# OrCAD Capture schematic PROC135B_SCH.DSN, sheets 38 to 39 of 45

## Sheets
38 38. CSI INTERFACE: size C; title: SOC CSI INTERFACE,  BIDIRECTIONAL PASSIVE SWITCH AND CAMERA CONNECTOR
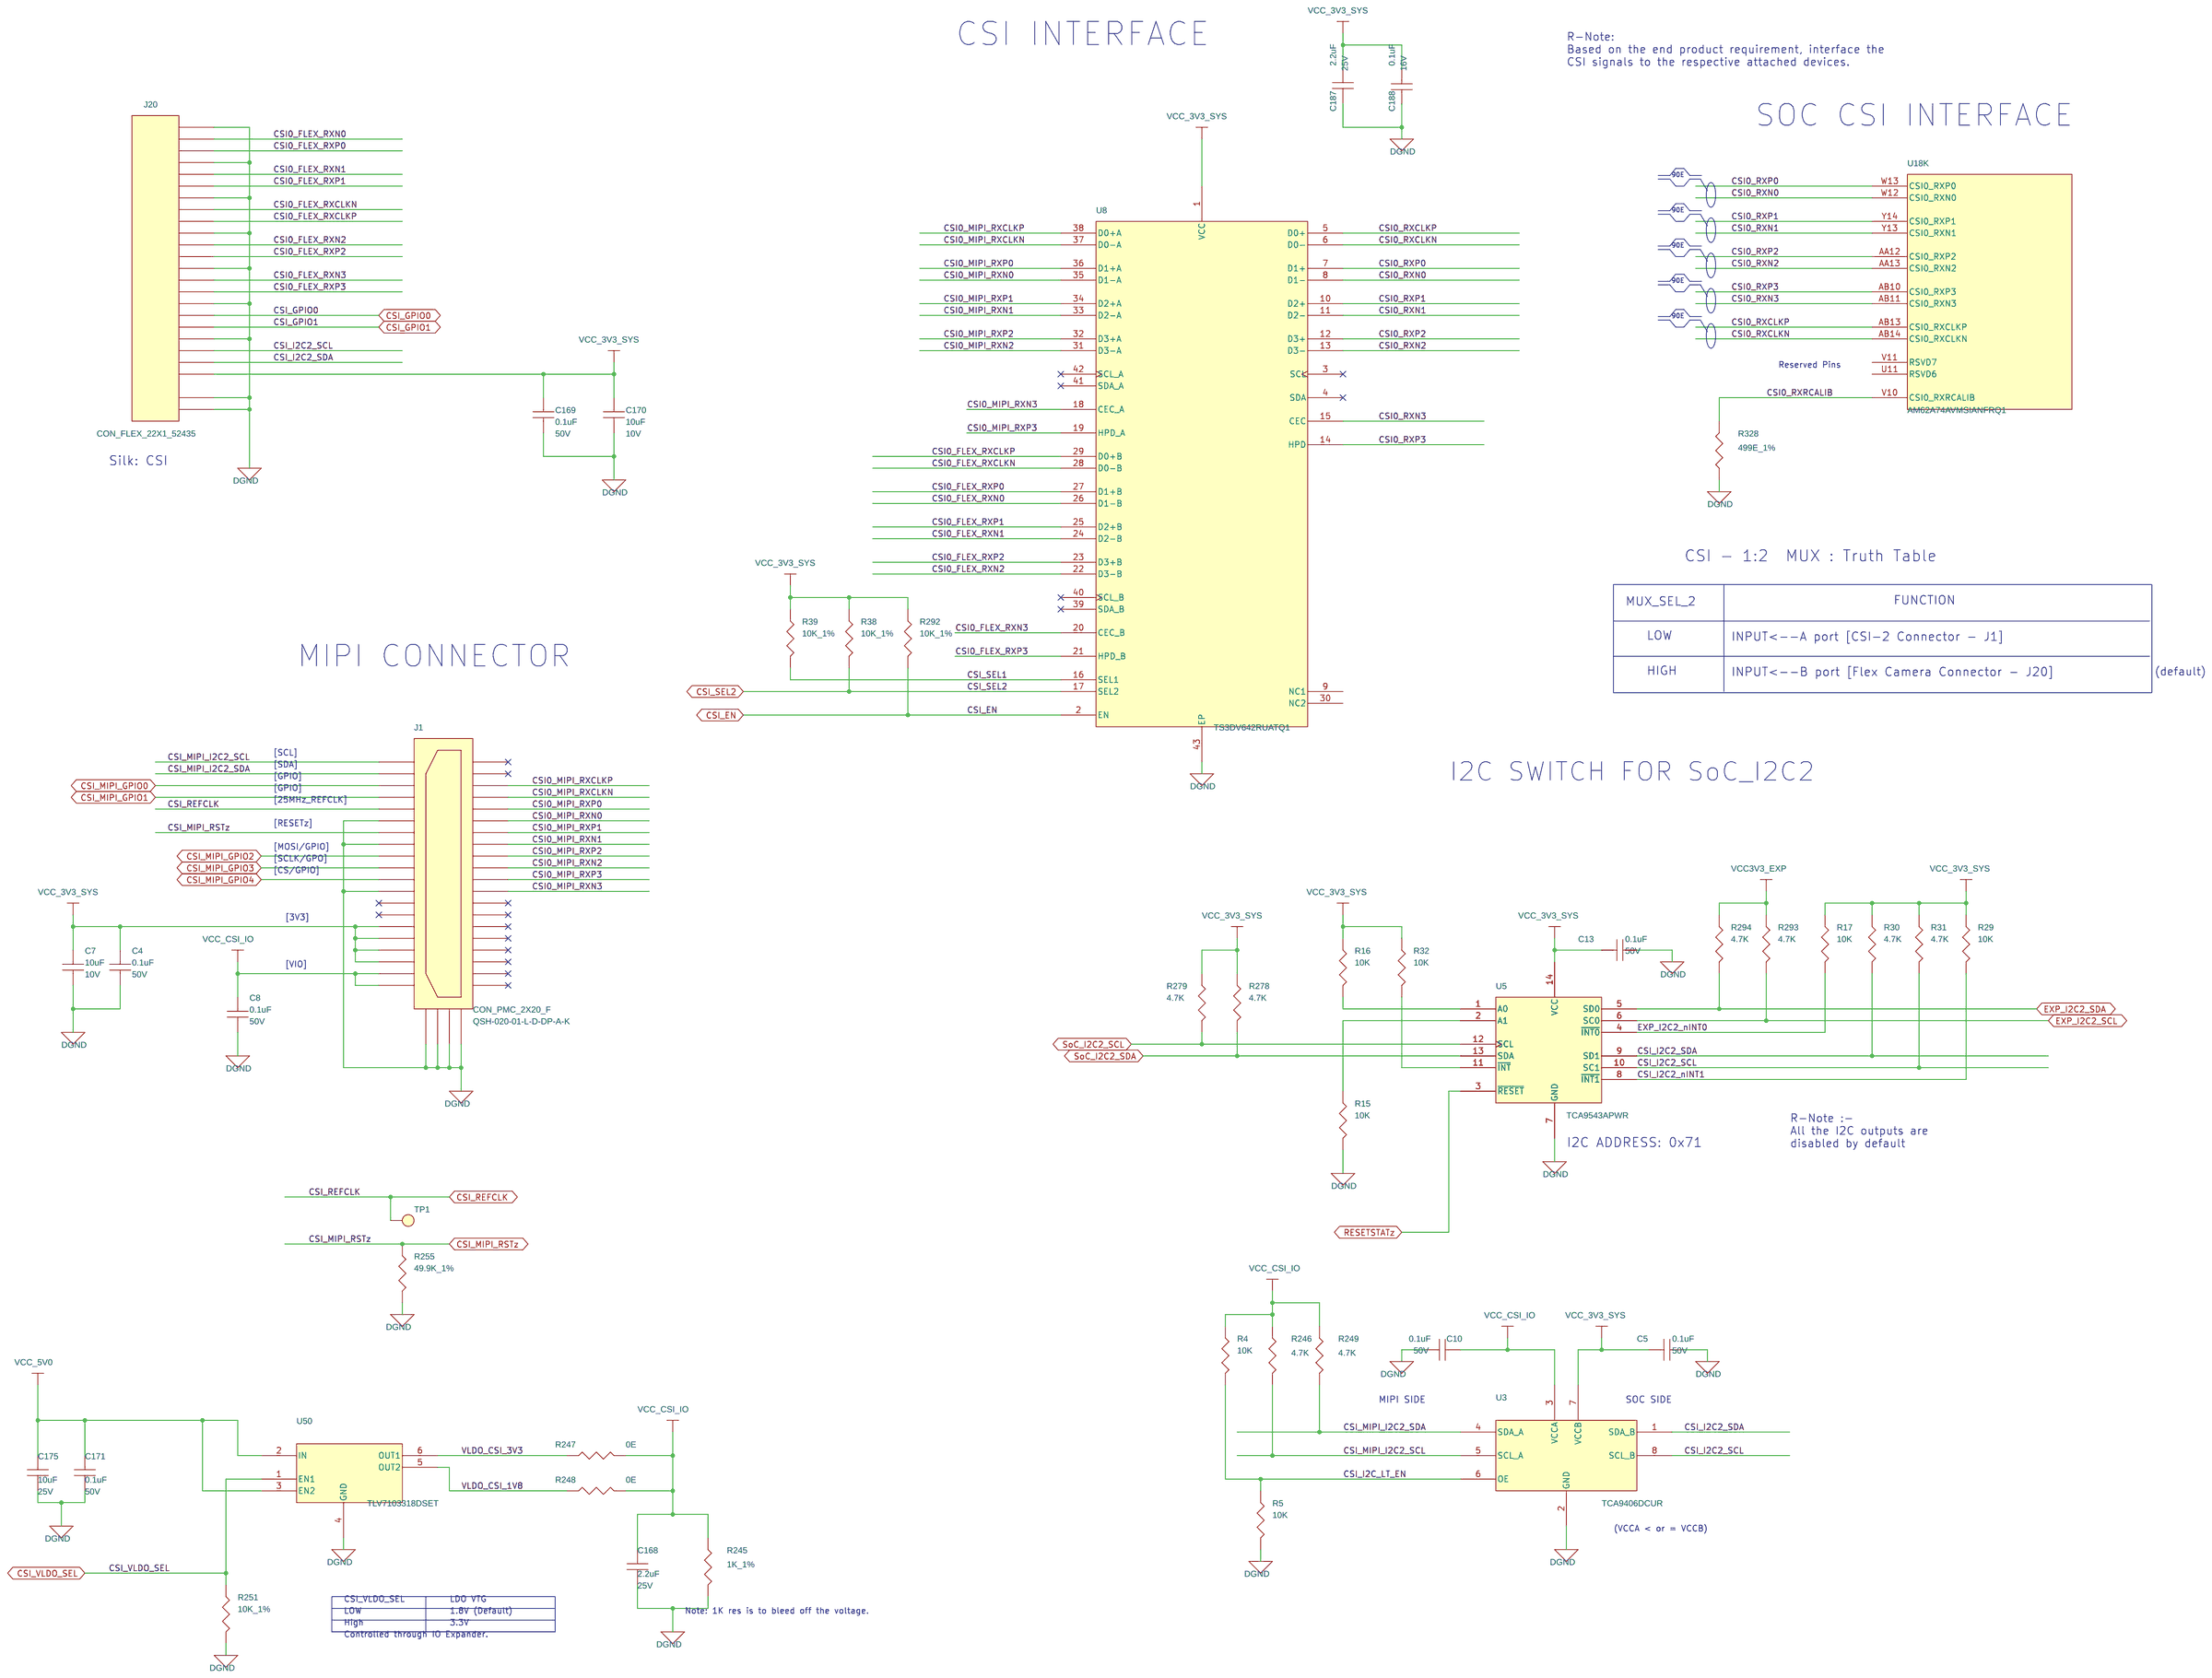
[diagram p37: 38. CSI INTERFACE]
39 39. AUDIO CODEC: size C; title: AUDIO CODEC
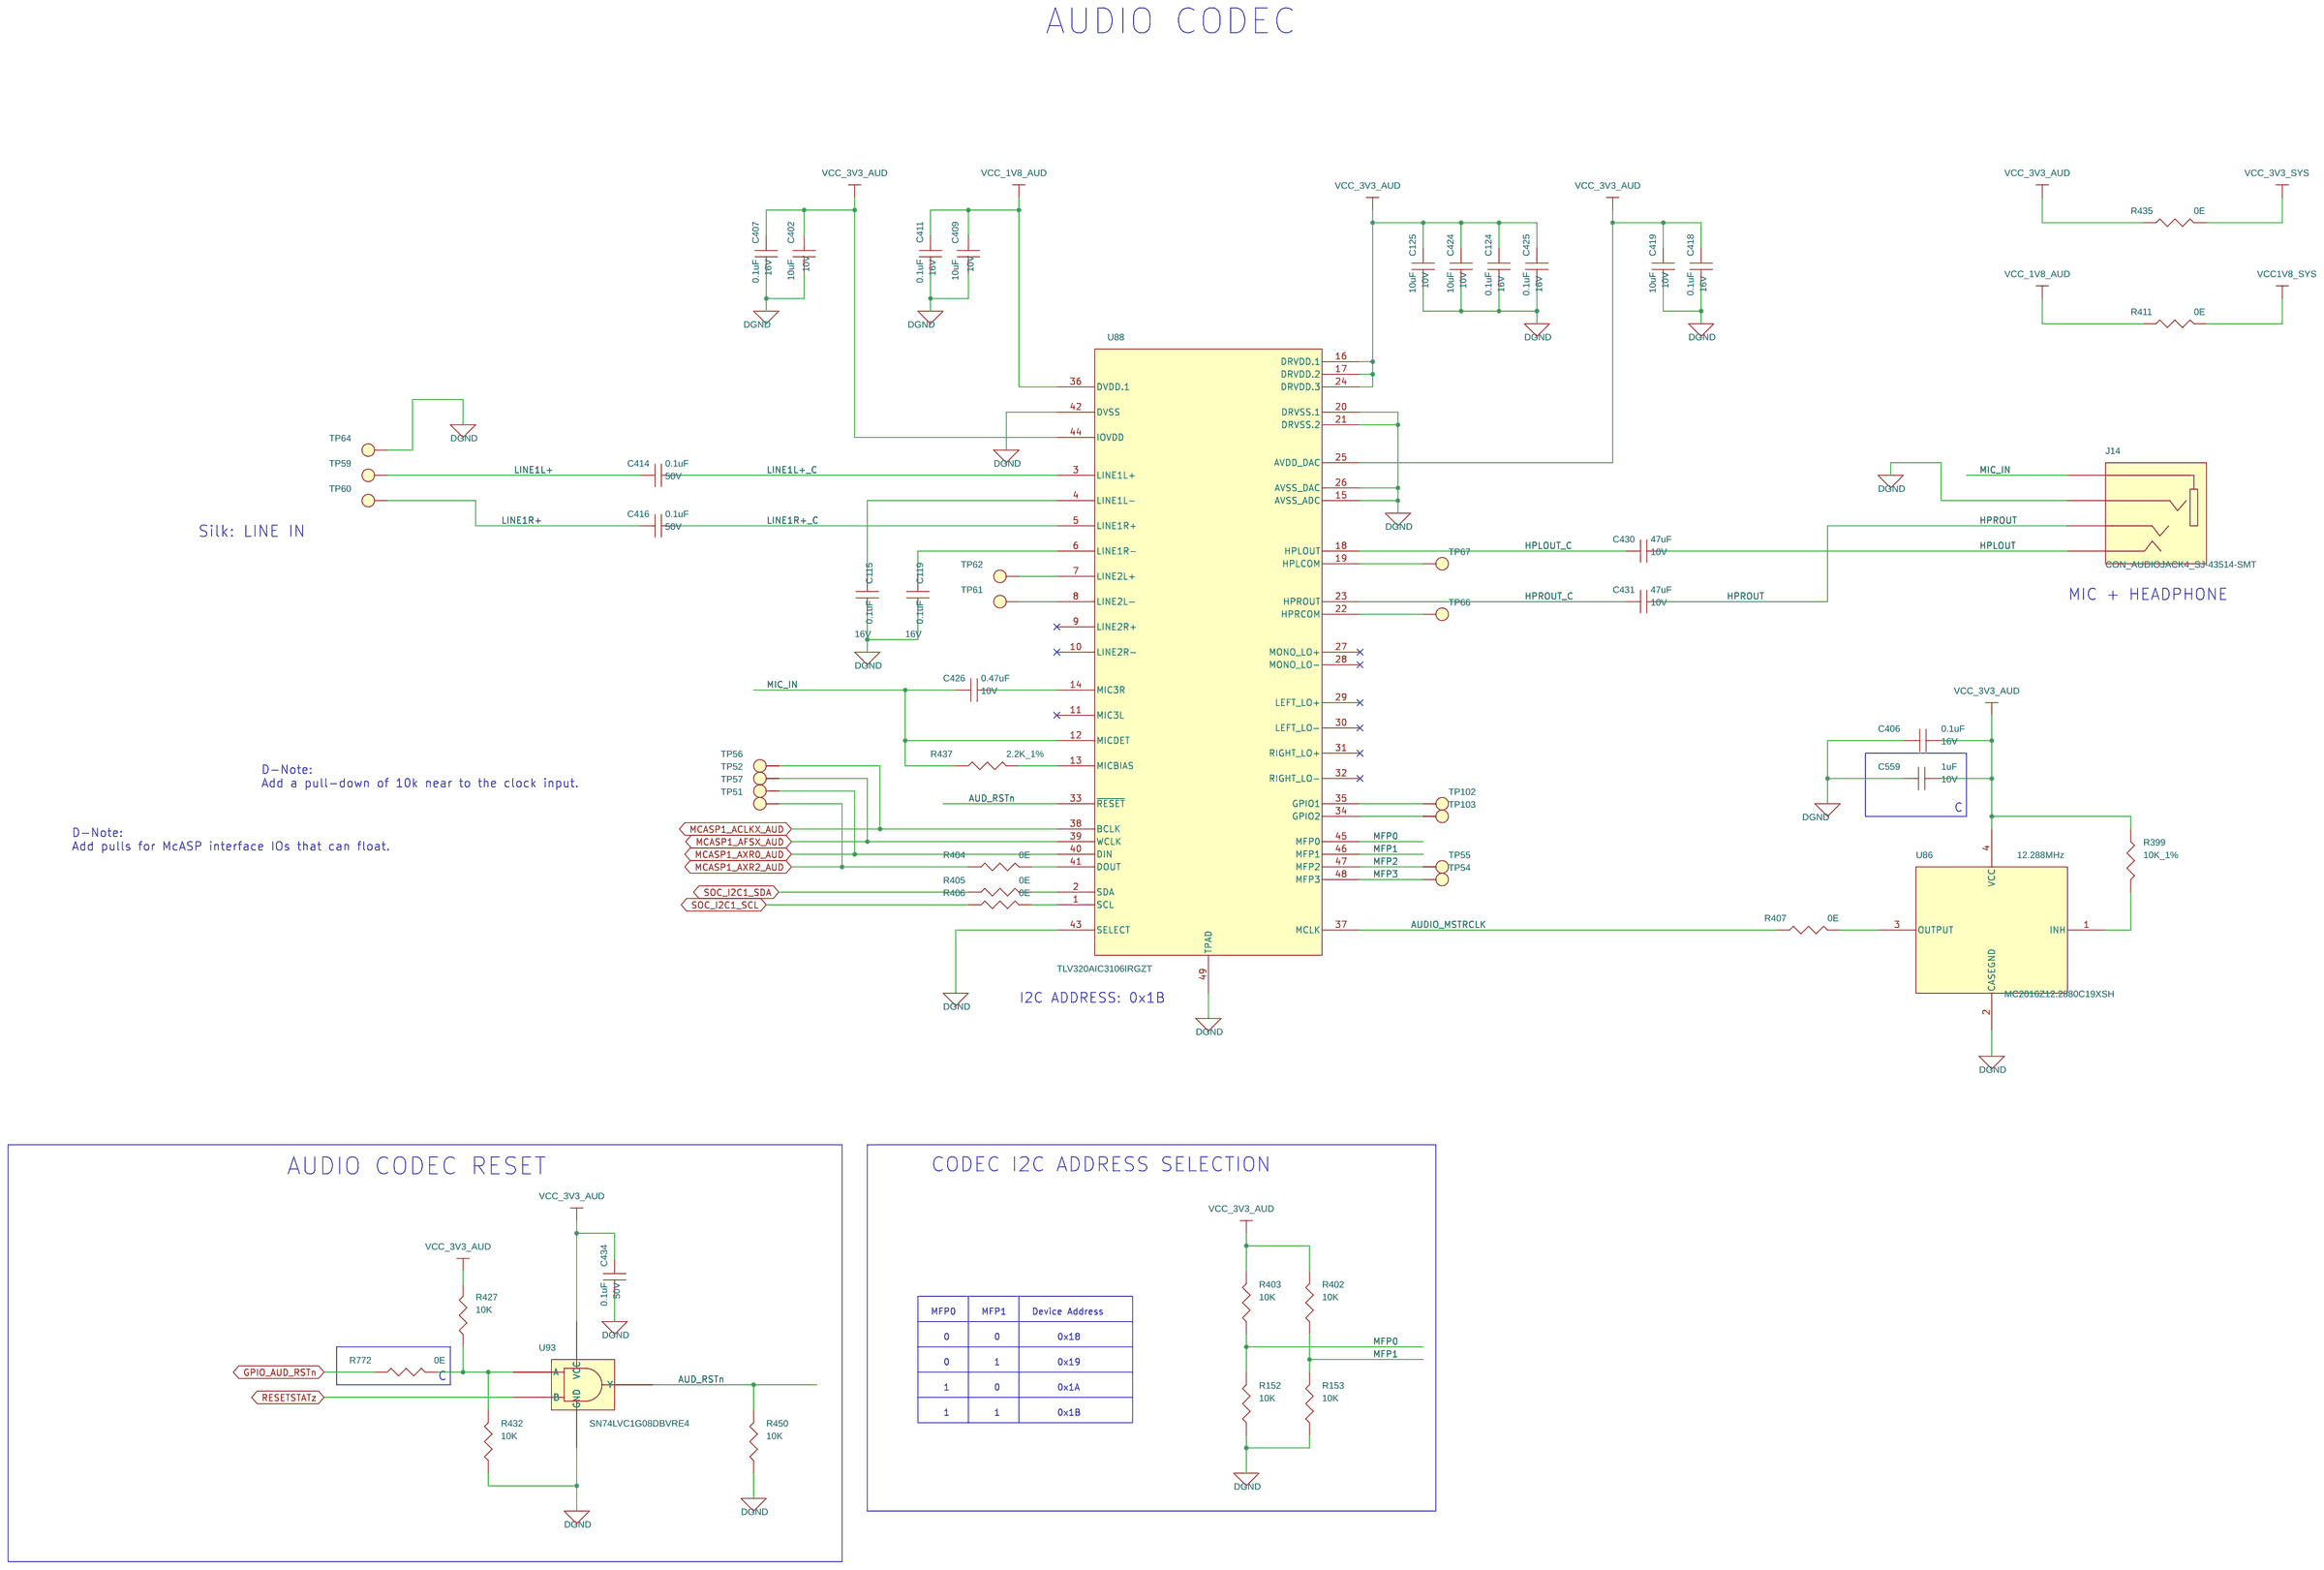
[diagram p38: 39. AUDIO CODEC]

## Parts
sheet 34. MCU HEADER
U18  AM62A74AVMSIANFRQ1  [FBGA484_31-49_710X710_2-7]  (sections A,B,C,D,E,F,G,H,I,J,K,L,M,N,O,P,Q)
sheet 38. CSI INTERFACE
C4  0.1uF  [CAP0402_0-75]
C5  0.1uF  [CAP0402_0-75]
C7  10uF  [CAP0402_0-75]
C8  0.1uF  [CAP0402_0-75]
C10  0.1uF  [CAP0402_0-75]
C13  0.1uF  [CAP0402_0-75]
C168  2.2uF  [CAP0402_0-75]
C169  0.1uF  [CAP0402_0-75]
C170  10uF  [CAP0402_0-75]
C171  0.1uF  [CAP0402_0-75]
C175  10uF  [CAP0805_1-5]
C187  2.2uF  [CAP0402_0-75]
C188  0.1uF  [CAP0201_0-5]
J1  CON_PMC_2X20_F  [CON_PMC2X20_QSH-020-01-D-DP-A_S_S_S_3-4]
J20  CON_FLEX_22X1_52435  [CON_FLEX22X1_52435_S_R_S]
R4  10K  [RES0201_0-5]
R5  10K  [RES0201_0-5]
R15  10K  [RES0201_0-5]
R16  10K  [RES0201_0-5]
R17  10K  [RES0201_0-5]
R29  10K  [RES0201_0-5]
R30  4.7K  [RES0201_0-5]
R31  4.7K  [RES0201_0-5]
R32  10K  [RES0201_0-5]
R38  10K_1%  [RES0402_0-5]
R39  10K_1%  [RES0402_0-5]
R245  1K_1%  [RES0402_0-5]
R246  4.7K  [RES0201_0-5]
R247  0E  [RES0402_0-5]
R248  0E  [RES0402_0-5]
R249  4.7K  [RES0201_0-5]
R251  10K_1%  [RES0402_0-5]
R255  49.9K_1%  [RES0402_0-5]
R278  4.7K  [RES0201_0-5]
R279  4.7K  [RES0201_0-5]
R292  10K_1%  [RES0402_0-5]
R293  4.7K  [RES0201_0-5]
R294  4.7K  [RES0201_0-5]
R328  499E_1%  [RES0402_0-5]
TP1  TP20_SMD  [TP20_SMD]
U3  TCA9406DCUR  [VSSOP8_19-68_85X95]
U5  TCA9543APWR  [TSSOP14_25-59_205X180_1-2]
U8  TS3DV642RUATQ1  [TQFN42_19-68_140X360_0-8]
U50  TLV7103318DSET  [WSON6_19-68_60X60]
sheet 39. AUDIO CODEC
C115  0.1uF  [CAP0201_0-5]
C119  0.1uF  [CAP0201_0-5]
C124  0.1uF  [CAP0201_0-5]
C125  10uF  [CAP0402_0-75]
C402  10uF  [CAP0402_0-75]
C406  0.1uF  [CAP0201_0-5]
C407  0.1uF  [CAP0201_0-5]
C409  10uF  [CAP0402_0-75]
C411  0.1uF  [CAP0201_0-5]
C414  0.1uF  [CAP0402_0-75]
C416  0.1uF  [CAP0402_0-75]
C418  0.1uF  [CAP0201_0-5]
C419  10uF  [CAP0402_0-75]
C424  10uF  [CAP0402_0-75]
C425  0.1uF  [CAP0201_0-5]
C426  0.47uF  [CAP0402_0-75]
C430  47uF  [CAP1206_2]
C431  47uF  [CAP1206_2]
C434  0.1uF  [CAP0402_0-75]
C559  1uF  [CAP0201_0-5]
J14  CON_AUDIOJACK4_SJ-43514-SMT  [CON_AV4_SJ-43514-SMT_S_R_S_5-1]
R152  10K  [RES0201_0-5]
R153  10K  [RES0201_0-5]
R399  10K_1%  [RES0201_0-5]
R402  10K  [RES0201_0-5]
R403  10K  [RES0201_0-5]
R404  0E  [RES0201_0-5]
R405  0E  [RES0201_0-5]
R406  0E  [RES0201_0-5]
R407  0E  [RES0201_0-5]
R411  0E  [RES0402_0-5]
R427  10K  [RES0201_0-5]
R432  10K  [RES0201_0-5]
R435  0E  [RES0402_0-5]
R437  2.2K_1%  [RES0201_0-5]
R450  10K  [RES0201_0-5]
R772  0E  [RES0201_0-5]
TP51  TP20_SMD  [TP20_SMD]
TP52  TP20_SMD  [TP20_SMD]
TP54  TP20_SMD  [TP20_SMD]
TP55  TP20_SMD  [TP20_SMD]
TP56  TP20_SMD  [TP20_SMD]
TP57  TP20_SMD  [TP20_SMD]
TP59  THRU HOLE  [TP_40X65]
TP60  THRU HOLE  [TP_40X65]
TP61  TP20_SMD  [TP20_SMD]
TP62  TP20_SMD  [TP20_SMD]
TP64  THRU HOLE  [TP_40X65]
TP66  TP20_SMD  [TP20_SMD]
TP67  TP20_SMD  [TP20_SMD]
TP102  TP20_SMD  [TP20_SMD]
TP103  TP20_SMD  [TP20_SMD]
U86  12.288MHz  [OSC4_KC2016K_80X60_SMD_0-8]
U88  TLV320AIC3106IRGZT  [VQFN48_19-68_285X285]
U93  SN74LVC1G08DBVRE4  [SOT23-5]

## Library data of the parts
U18 = AM62A-EVM_SOC_FCBGA484: IC AM62A SK EVM SoC MICROPROCESSOR FCBGA484; Chkd/date: PRADEEP/120225; Crtd /date: SHANKARI/120225; Custom_Duty: 15%; Customs_HS_Code: 85369090; Distributor_name: NA; Distributor_part_number: NA; Footprint Path: Y:\MIS_DATABASE\Library\ALTIUM_TOOL\PCB_FOOTPRINTS\Altium_Footprint_Lib.PcbLib; Height: 2.65MM; Library Path: Y:\MIS_DATABASE\Library\ALTIUM_TOOL\SCHEMATICS_PARTS\MS_MICROPROCESSOR_Library.schlib; Library Ref: AM62A-EVM_SoC_FCBGA484; Mfr_name: TEXAS INSTRUMENTS; Mistral Part No: 141225020003-R; Package: FCBGA484; Part_type: ICS\DIGITAL\MICROPROCESSOR; Project: AM62A_SK_EVM; RoHS: NA; Temperature: NA; Tolerance: NA; Voltage: NA; Wattage: NA; Weight: NA; Datasheet: Y:\MIS_DATABASE\DATASHEETS\ICS\DIGITAL\MICROCONTROLLER\AM62A_SK_EVM.PDF
C4 C5 C8 C10 C13 C169 C171 = CAP: CAP CERAMIC 0.1uF 50V 10% X7R AUTO 0402; Alt_Mfr_name: YAGEO AMERICA; Alt_Mfr_part_number: CC0402KRX5R8BB104; Chkd/date: MANIRAJA/250221; Crtd /date: ALVY/240221; Custom_Duty: 15%; Customs_HS_Code: 85322990; Distributor_name: MOUSER; Distributor_part_number: 81-GRT155R71H104KE1D; Footprint Path: Y:\MIS_DATABASE\Library\ALTIUM_TOOL\PCB_FOOTPRINTS\Altium_Footprint_Lib.PcbLib; Height: 0.55MM; Library Path: Y:\MIS_DATABASE\Library\ALTIUM_TOOL\SCHEMATICS_PARTS\MS_DISCRETE_Library.schlib; Mfr_name: MURATA; Mfr_part_number: GRT155R71H104KE01D; Mistral Part No: 120019030005-R; Package: 0402; Part_type: CAPACITORS\CERAMIC; Project: TI_DRA821 SK EVM BRD; RoHS: RoHS; Temperature: -55°C+125°C; Tolerance: 10%; Voltage: 50V; Wattage: NA; Weight: NA; Datasheet: Y:\MIS_DATABASE\DATASHEETS\CAPACITORS\GRT155R71H104KE01.PDF
C7 C125 C170 C402 C409 C419 C424 = CAP: CAP CERAMIC 10uF 10V 20% X5R 0402; Chkd/date: PRADEEP/130623; Crtd /date: PRADEEP/130623; Custom_Duty: 15%; Customs_HS_Code: 85322990; Distributor_name: NA; Distributor_part_number: NA; Footprint Path: Y:\MIS_DATABASE\Library\ALTIUM_TOOL\PCB_FOOTPRINTS\Altium_Footprint_Lib.PcbLib; Height: 0.55MM; Library Path: Y:\MIS_DATABASE\Library\ALTIUM_TOOL\SCHEMATICS_PARTS\MS_DISCRETE_Library.schlib; Mfr_name: MURATA; Mfr_part_number: GRM155R61A106ME18; Mistral Part No: 120022060018-R; Package: 0402; Part_type: CAPACITORS\CERAMIC; Project: AM62P_SK; RoHS: RoHS; Temperature: -55°C+85°C; Tolerance: 20%; Voltage: 10V; Wattage: NA; Weight: 6mg; Datasheet: Y:\MIS_DATABASE\DATASHEETS\CAPACITORS\MURATA-GXX-SER_NOV17.PDF
C168 = CAP: CAP CERAMIC 2.2uF 25V 10% X5R AUTO 0402; Chkd/date: MANIRAJA/240920; Crtd /date: ALVY/240920; Custom_Duty: 15%; Customs_HS_Code: 85322990; Distributor_name: DIGIKEY; Distributor_part_number: 490-12267-1-ND; Footprint Path: Y:\MIS_DATABASE\Library\ALTIUM_TOOL\PCB_FOOTPRINTS\Altium_Footprint_Lib.PcbLib; Height: 0.70MM; Library Path: Y:\MIS_DATABASE\Library\ALTIUM_TOOL\SCHEMATICS_PARTS\MS_DISCRETE_Library.schlib; Manufacturer: MURATA; Mfr_name: MURATA; Mfr_part_number: GRT155R61E225KE13D; Mistral Part No: 120020090019-R; Package: 0402; Part_type: CAPACITORS\CERAMIC; Project: ECU_RO; RoHS: RoHS; Temperature: -55°C+85°C; Tolerance: 10%; Voltage: 25V; Wattage: NA; Weight: 0.65mg; Datasheet: Y:\MIS_DATABASE\DATASHEETS\CAPACITORS\GRT155R61E225KE13.PDF
C175 = CAP: CAP CERAMIC 10uF 25V 10% X7S 0805; Chkd/date: PRADEEP/130623; Crtd /date: PRADEEP/130623; Custom_Duty: 15%; Customs_HS_Code: 85322990; Distributor_name: DIGIKEY; Distributor_part_number: 490-GRT21BC71E106KE13LCT-ND; Footprint Path: Y:\MIS_DATABASE\Library\ALTIUM_TOOL\PCB_FOOTPRINTS\Altium_Footprint_Lib.PcbLib; Height: 1.45MM; Library Path: Y:\MIS_DATABASE\Library\ALTIUM_TOOL\SCHEMATICS_PARTS\MS_DISCRETE_Library.schlib; Manufacturer: MURATA; Mfr_name: MURATA; Mfr_part_number: GRT21BC71E106KE13L; Mistral Part No: 120022060025-R; Package: 0805; Part_type: CAPACITORS\CERAMIC; Project: AM62P_SK; RoHS: RoHS; Temperature: -55°C+125°C; Tolerance: 10%; Voltage: 25V; Wattage: NA; Weight: 5.5mg; Datasheet: Y:\MIS_DATABASE\DATASHEETS\CAPACITORS\GRT21BC71E106KE13L.PDF
C187 = CAP: CAP CERAMIC 2.2uF 25V 10% X5R AUTO 0402; Chkd/date: MANIRAJA/240920; Crtd /date: ALVY/240920; Custom_Duty: 15%; Customs_HS_Code: 85322990; Distributor_name: DIGIKEY; Distributor_part_number: 490-12267-1-ND; Footprint Path: Y:\MIS_DATABASE\Library\ALTIUM_TOOL\PCB_FOOTPRINTS\Altium_Footprint_Lib.PcbLib; Height: 0.70MM; Library Path: Y:\MIS_DATABASE\Library\ALTIUM_TOOL\SCHEMATICS_PARTS\MS_DISCRETE_Library.schlib; Mfr_name: MURATA; Mfr_part_number: GRT155R61E225KE13D; Mistral Part No: 120020090019-R; Package: 0402; Part_type: CAPACITORS\CERAMIC; Project: ECU_RO; RoHS: RoHS; Temperature: -55°C+85°C; Tolerance: 10%; Voltage: 25V; Wattage: NA; Weight: 0.65mg; Datasheet: Y:\MIS_DATABASE\DATASHEETS\CAPACITORS\GRT155R61E225KE13.PDF
C188 = CAP: CAP CERAMIC 0.1uF 16V 10% X5R 0201; Alt_Mfr_name: YAGEO AMERICA; Alt_Mfr_part_number: CC0402KRX5R8BB104; Chkd/date: PRADEEP/130623; Crtd /date: PRADEEP/130623; Custom_Duty: 15%; Customs_HS_Code: 85322990; Distributor_name: NA; Distributor_part_number: NA; Footprint Path: Y:\MIS_DATABASE\Library\ALTIUM_TOOL\PCB_FOOTPRINTS\Altium_Footprint_Lib.PcbLib; Height: 0.33MM; Library Path: Y:\MIS_DATABASE\Library\ALTIUM_TOOL\SCHEMATICS_PARTS\MS_DISCRETE_Library.schlib; Mfr_name: MURATA; Mfr_part_number: GRT033R61C104KE01; Mistral Part No: 120022060019-R; Package: 0201; Part_type: CAPACITORS\CERAMIC; Project: AM62P_SK; RoHS: RoHS; Temperature: -55°C+85°C; Tolerance: 10%; Voltage: 16V; Wattage: NA; Weight: 0.33mg; Datasheet: Y:\MIS_DATABASE\DATASHEETS\CAPACITORS\GRT033R61C104KE01XX.PDF
J1 = CON_PMC_20X2_F_DP_TI: CON PMC 2X20 0.50MM PITCH FEMALE ST SMD; Chkd/date: MANIRAJA/251018; Crtd /date: ALVY/251018; Custom_Duty: 24%; Customs_HS_Code: 85369090; Distributor_name: DIGIKEY; Distributor_part_number: SAM10648-ND; Footprint Path: Y:\MIS_DATABASE\Library\ALTIUM_TOOL\PCB_FOOTPRINTS\Altium_Footprint_Lib.PcbLib; Height: 3.33MM; Library Path: Y:\MIS_DATABASE\Library\ALTIUM_TOOL\SCHEMATICS_PARTS\MS_CONNECTOR_Library.schlib; Library Ref: CON_PMC_20X2_F_DP; Mfr_name: SAMTEC; Mfr_part_number: QSH-020-01-L-D-DP-A-K; Mistral Part No: 150018100049-R; Package: SMD; Part_type: CONNECTOR\PMC; Project: TI_J7ES_EVM_CP; RoHS: RoHS; Temperature: -55°C+125°C; Tolerance: NA; Voltage: NA; Wattage: NA; Weight: NA; Datasheet: Y:\MIS_DATABASE\DATASHEETS\CONNECTORS\QSH-SERIES.PDF
J20 = CON_22X1_2SH: CON FPC 22X1 0.50MM PITCH TPM RT SMD; Chkd/date: PRAVEEN/090822; Crtd /date: PRAVEEN/090822; Custom_Duty: 24%; Customs_HS_Code: 85369090; Distributor_name: DIGIKEY; Distributor_part_number: WM6753CT-ND; Height: 2.00MM; Mfr_name: MOLEX; Mfr_part_number: 52435-2271; Mistral Part No: 150022080019-R; Package: SMD; Part_type: CONNECTOR\FPC; Project: JHAHP_SVB; RoHS: RoHS; Temperature: -20°C to +85°C; Tolerance: NA; Voltage: NA; Wattage: NA; Datasheet: Y:\MIS_DATABASE\DATASHEETS\CONNECTORS\52435.PDF
R4 R5 R15-R17 R29 R32 R152 R153 R402 R403 R427 R432 R450 = RESISTOR: RES 10K 1/20W 5% 0201; Chkd/date: MANIRAJA/050517; Crtd /date: MANIRAJA/050517; Custom_Duty: 15%; Customs_HS_Code: 85332119; Distributor_name: DIGIKEY; Distributor_part_number: 311-10KNCT-ND; Footprint Path: Y:\MIS_DATABASE\Library\ALTIUM_TOOL\PCB_FOOTPRINTS\Altium_Footprint_Lib.PcbLib; Height: 0.26MM; Library Path: Y:\MIS_DATABASE\Library\ALTIUM_TOOL\SCHEMATICS_PARTS\MS_DISCRETE_Library.schlib; Mfr_name: YAGEO AMERICA; Mfr_part_number: RC0201JR-0710KL; Mistral Part No: 110010070051-R; Package: 0201; Part_type: RESISTORS\FIXED; Project: GOLDEN-I LITE; RoHS: RoHS; Temperature: -55°C+125°C; Tolerance: 5%; Voltage: NA; Wattage: 1/20W; Weight: 0.17mg; Datasheet: Y:\MIS_DATABASE\DATASHEETS\RESISTORS\RCXXXXL-SER_MAR18.PDF
R30 R31 R246 R249 R278 R279 R293 R294 = RESISTOR: RES 4.7K 1/20W 5% 0201; Chkd/date: MANIRAJA/200921; Crtd /date: ALVY/200921; Custom_Duty: 15%; Customs_HS_Code: 85332119; Distributor_name: DIGIKEY; Distributor_part_number: 311-4.7KNCT-ND; Footprint Path: Y:\MIS_DATABASE\Library\ALTIUM_TOOL\PCB_FOOTPRINTS\Altium_Footprint_Lib.PcbLib; Height: 0.26MM; Library Path: Y:\MIS_DATABASE\Library\ALTIUM_TOOL\SCHEMATICS_PARTS\MS_DISCRETE_Library.schlib; Mfr_name: YAGEO AMERICA; Mfr_part_number: RC0201JR-074K7L; Mistral Part No: 110021090007-R; Package: 0201; Part_type: RESISTORS\FIXED; Project: TI_AM62x SKEVM_BRD; RoHS: RoHS; Temperature: -55°C+125°C; Tolerance: 5%; Voltage: NA; Wattage: 1/20W; Weight: 0.17mg; Datasheet: Y:\MIS_DATABASE\DATASHEETS\RESISTORS\RCXXXXL-SER_MAR18.PDF
R38 R39 R251 R292 = RESISTOR: RES 10K 1/10W 1% AUTO 0402; Chkd/date: MANIRAJA/191020; Crtd /date: ALVY/191020; Custom_Duty: 15%; Customs_HS_Code: 85332119; Distributor_name: DIGIKEY; Distributor_part_number: MCS0402-10.0K-MFCT-ND; Footprint Path: Y:\MIS_DATABASE\Library\ALTIUM_TOOL\PCB_FOOTPRINTS\Altium_Footprint_Lib.PcbLib; Height: 0.37MM; Library Path: Y:\MIS_DATABASE\Library\ALTIUM_TOOL\SCHEMATICS_PARTS\MS_DISCRETE_Library.schlib; Manufacturer: VISHAY; Mfr_name: VISHAY; Mfr_part_number: MCS0402MC1002FE000; Mistral Part No: 110020100039-R; Package: 0402; Part_type: RESISTORS\FIXED; Project: MCX_80MHz_ADC_DRIVER; RoHS: RoHS; Temperature: -55°C+175°C; Tolerance: 1%; Voltage: NA; Wattage: 1/10W; Weight: 0.65mg; Datasheet: Y:\MIS_DATABASE\DATASHEETS\RESISTORS\MCTXXXXM-SER.PDF
R245 = RESISTOR: RES 1K 1/10W 1% 0402; Chkd/date: VASANTHA/281216; Crtd /date: MAZHAR/150506; Custom_Duty: 15%; Customs_HS_Code: 85332119; Distributor_name: DIGIKEY; Distributor_part_number: P1.00KLCT-ND; Footprint Path: Y:\MIS_DATABASE\Library\ALTIUM_TOOL\PCB_FOOTPRINTS\Altium_Footprint_Lib.PcbLib; Height: 0.40MM; Library Path: Y:\MIS_DATABASE\Library\ALTIUM_TOOL\SCHEMATICS_PARTS\MS_DISCRETE_Library.schlib; Mfr_name: PANASONIC-ECG; Mfr_part_number: ERJ-2RKF1001X; Mistral Part No: 110009030411-R; Package: 0402; Part_type: RESISTORS\FIXED; Project: VOCERA; RoHS: RoHS; Temperature: -55°C+155°C; Tolerance: 1%; Voltage: NA; Wattage: 1/10W; Weight: 0.8mg; Datasheet: Y:\MIS_DATABASE\DATASHEETS\RESISTORS\PAN-ERJSER_NOV17.PDF
R247 R248 = RESISTOR: RES 0E 1/16W JUMPER 0402; Chkd/date: VASANTHA/201216; Crtd /date: MUDDU/190810; Custom_Duty: 15%; Customs_HS_Code: 85332119; Distributor_name: DIGIKEY; Distributor_part_number: 541-0.0JCT-ND; Footprint Path: Y:\MIS_DATABASE\Library\ALTIUM_TOOL\PCB_FOOTPRINTS\Altium_Footprint_Lib.PcbLib; Height: 0.40MM; Library Path: Y:\MIS_DATABASE\Library\ALTIUM_TOOL\SCHEMATICS_PARTS\MS_DISCRETE_Library.schlib; Manufacturer: VISHAY; Mfr_name: VISHAY; Mfr_part_number: CRCW04020000Z0ED; Mistral Part No: 110010080019-R; Package: 0402; Part_type: RESISTORS\FIXED; Project: PB_BUGBASE; RoHS: RoHS; Temperature: -55°C+155°C; Tolerance: NA; Voltage: NA; Wattage: 1/16W; Weight: 0.65mg; Datasheet: Y:\MIS_DATABASE\DATASHEETS\RESISTORS\CRCW0603.PDF
R255 = RESISTOR: RES 49.9K 1/10W 1% 0402; Chkd/date: MANIRAJA/130617; Crtd /date: BAVISH/020611; Custom_Duty: 15%; Customs_HS_Code: 85332119; Distributor_name: DIGIKEY; Distributor_part_number: P49.9KLCT-ND; Footprint Path: Y:\MIS_DATABASE\Library\ALTIUM_TOOL\PCB_FOOTPRINTS\Altium_Footprint_Lib.PcbLib; Height: 0.40MM; Library Path: Y:\MIS_DATABASE\Library\ALTIUM_TOOL\SCHEMATICS_PARTS\MS_DISCRETE_Library.schlib; Manufacturer: VISHAY; Mfr_name: PANASONIC-ECG; Mfr_part_number: ERJ-2RKF4992X; Mistral Part No: 110011060018-R; Package: 0402; Part_type: RESISTORS\FIXED; Project: AM4515_EVM_LCD; RoHS: RoHS; Temperature: -55°C+155°C; Tolerance: 1%; Voltage: NA; Wattage: 1/10W; Weight: 0.8mg; Datasheet: Y:\MIS_DATABASE\DATASHEETS\RESISTORS\PAN-ERJSER_NOV17.PDF
R328 = RESISTOR: RES 499E 1/16W 1% 0402; Chkd/date: MANIRAJA/051020; Crtd /date: ALVY/051020; Custom_Duty: 15%; Customs_HS_Code: 85332119; Distributor_name: DIGIKEY; Distributor_part_number: 311-499LRCT-ND; Footprint Path: Y:\MIS_DATABASE\Library\ALTIUM_TOOL\PCB_FOOTPRINTS\Altium_Footprint_Lib.PcbLib; Height: 0.40MM; Library Path: Y:\MIS_DATABASE\Library\ALTIUM_TOOL\SCHEMATICS_PARTS\MS_DISCRETE_Library.schlib; Mfr_name: YAGEO AMERICA; Mfr_part_number: RC0402FR-07499RL; Mistral Part No: 110020080006-R; Package: 0402; Part_type: RESISTORS\FIXED; Project: AM64XX_EVM; RoHS: RoHS; Temperature: -55°C+155°C; Tolerance: 1%; Voltage: NA; Wattage: 1/16W; Weight: 0.65mg; Datasheet: Y:\MIS_DATABASE\DATASHEETS\RESISTORS\RCXXXXL-SER_MAR18.PDF
TP1 TP51 TP52 TP54-TP57 TP61 TP62 TP66 TP67 TP102 TP103 = TESTPOINT: TESTPOINT CIR 20 SMD; Chkd/date: SHREESHAIL/171006; Crtd /date: MAZHAR/171006; Custom_Duty: NA; Customs_HS_Code: NA; Distributor_name: NA; Distributor_part_number: NA; Footprint Path: Y:\MIS_DATABASE\Library\ALTIUM_TOOL\PCB_FOOTPRINTS\Altium_Footprint_Lib.PcbLib; Height: NA; Library Path: Y:\MIS_DATABASE\Library\ALTIUM_TOOL\SCHEMATICS_PARTS\MS_DISCRETE_Library.schlib; MECHANICAL 3D STEP FILE: NA; Mfr_name: LOCAL; Mistral Part No: NA; Package: SMD; Project: BT MODULE_CSRBC04; RoHS: NA; Temperature: NA; Tolerance: NA; Voltage: NA; Wattage: NA; Weight: NA; Datasheet: NA
U3 = TCA9406DCUR_VSSOP8: IC VOLTAGE-LEVEL TRANSLATOR 2BIT BIDIRECTIONAL VSSOP8; Chkd/date: USMAN/190612; Crtd /date: BAVISH/210611; Custom_Duty: 15%; Customs_HS_Code: 85423100; Distributor_name: DIGIKEY; Distributor_part_number: 296-28109-1-ND; Footprint Path: Y:\MIS_DATABASE\Library\ALTIUM_TOOL\PCB_FOOTPRINTS\Altium_Footprint_Lib.PcbLib; Height: 0.90MM; Library Path: Y:\MIS_DATABASE\Library\ALTIUM_TOOL\SCHEMATICS_PARTS\MS_MISCINTERFACE_Library.schlib; Mfr_name: TEXAS INSTRUMENTS; Mistral Part No: 141011060026-R; Package: VSSOP8; Part_type: ICS\INTERFACE; Project: SVDU; RoHS: RoHS; Temperature: -40°C+85°C; Tolerance: NA; Voltage: NA; Wattage: NA; Weight: NA; Datasheet: Y:\MIS_DATABASE\DATASHEETS\ICS\INTERFACE\TCA9406.PDF
U5 = TCA9543APWR_TSSOP14: IC 2-CHANNEL I2C BUS SWITCH WITH INTERRUPT LOGIC AND RESET TSSOP14; Chkd/date: VASANTHA/060516; Crtd /date: VASANTHA/070316; Custom_Duty: 15%; Customs_HS_Code: 85423100; Distributor_name: DIGIKEY; Distributor_part_number: 296-42157-1-ND; Footprint Path: Y:\MIS_DATABASE\Library\ALTIUM_TOOL\PCB_FOOTPRINTS\Altium_Footprint_Lib.PcbLib; Height: 1.20MM; Library Path: Y:\MIS_DATABASE\Library\ALTIUM_TOOL\SCHEMATICS_PARTS\MS_BUSDRIVERTRANSCEIVER_Library.schlib; Manufacturer: TEXAS INSTRUMENTS; Mfr_name: TEXAS INSTRUMENTS; Mistral Part No: 141016030006-R; Package: TSSOP14; Part_type: ICS\DIGITAL\BUSTRANSCEIVER; Project: OCTASIC_3600; RoHS: RoHS; Temperature: -40°C+85°C; Tolerance: NA; Voltage: NA; Wattage: NA; Weight: NA; Datasheet: Y:\MIS_DATABASE\DATASHEETS\ICS\DIGITAL\BUSTRANSCEIVER\TCA9543A.PDF
U8 = TS3DV642-Q1_WQFN42: IC 8Gbps 12-CHANNEL DIFFERENTIAL 1:2 AND 2:1 MUX WQFN42; Chkd/date: MANIRAJA/170221; Crtd /date: ALVY/170221; Custom_Duty: 15%; Customs_HS_Code: 85423100; Distributor_name: NA; Distributor_part_number: NA; Footprint Path: Y:\MIS_DATABASE\Library\ALTIUM_TOOL\PCB_FOOTPRINTS\Altium_Footprint_Lib.PcbLib; Height: 0.80MM; Library Path: Y:\MIS_DATABASE\Library\ALTIUM_TOOL\SCHEMATICS_PARTS\MS_COMBINATIONAL_Library.schlib; Mfr_name: TEXAS INSTRUMENTS; Mistral Part No: 141021020023-R; Package: WQFN42; Part_type: ICS\DIGITAL\COMBINATIONAL; Project: J7ES_SK_BRD; RoHS: RoHS; Temperature: -40°C+105°C; Tolerance: NA; Voltage: NA; Wattage: NA; Weight: NA; Datasheet: Y:\MIS_DATABASE\DATASHEETS\ICS\DIGITAL\COMBINATIONAL\TS3DV642-Q1.PDF
U50 = TLV7103318D_WSON6: IC REGULATOR LDO LINEAR 200mA WSON6; Chkd/date: NAVEED/080415; Crtd /date: JEBRAN/300315; Custom_Duty: 15%; Customs_HS_Code: 85423100; Distributor_name: DIGIKEY; Distributor_part_number: 296-29058-1-ND; Height: 0.80MM; Manufacturer: TEXAS INSTRUMENTS; Mfr_name: TEXAS INSTRUMENTS; Mistral Part No: 142015030017-R; Package: WSON6; Part_type: ICS\POWER\VOLTAGE REGULATOR; Project: DUET BOARDS; RoHS: RoHS; Temperature: -40°C+125°C; Tolerance: NA; Voltage: NA; Wattage: NA; Weight: NA; Datasheet: Y:\MIS_DATABASE\DATASHEETS\MISC\REGULATORS\TLV71-SER.PDF
C115 C119 C124 C406 C407 C411 C418 C425 = CAP: CAP CERAMIC 0.1uF 16V 10% X5R 0201; Chkd/date: PRADEEP/130623; Crtd /date: PRADEEP/130623; Custom_Duty: 15%; Customs_HS_Code: 85322990; Distributor_name: NA; Distributor_part_number: NA; Footprint Path: Y:\MIS_DATABASE\Library\ALTIUM_TOOL\PCB_FOOTPRINTS\Altium_Footprint_Lib.PcbLib; Height: 0.33MM; Library Path: Y:\MIS_DATABASE\Library\ALTIUM_TOOL\SCHEMATICS_PARTS\MS_DISCRETE_Library.schlib; Mfr_name: MURATA; Mfr_part_number: GRT033R61C104KE01; Mistral Part No: 120022060019-R; Package: 0201; Part_type: CAPACITORS\CERAMIC; Project: AM62P_SK; RoHS: RoHS; Temperature: -55°C+85°C; Tolerance: 10%; Voltage: 16V; Wattage: NA; Weight: 0.33mg; Datasheet: Y:\MIS_DATABASE\DATASHEETS\CAPACITORS\GRT033R61C104KE01XX.PDF
C414 C416 C434 = CAP: CAP CERAMIC 0.1uF 50V 10% X7R AUTO 0402; Chkd/date: MANIRAJA/250221; Crtd /date: ALVY/240221; Custom_Duty: 15%; Customs_HS_Code: 85322990; Distributor_name: MOUSER; Distributor_part_number: 81-GRT155R71H104KE1D; Footprint Path: Y:\MIS_DATABASE\Library\ALTIUM_TOOL\PCB_FOOTPRINTS\Altium_Footprint_Lib.PcbLib; Height: 0.55MM; Library Path: Y:\MIS_DATABASE\Library\ALTIUM_TOOL\SCHEMATICS_PARTS\MS_DISCRETE_Library.schlib; Mfr_name: MURATA; Mfr_part_number: GRT155R71H104KE01D; Mistral Part No: 120019030005-R; Package: 0402; Part_type: CAPACITORS\CERAMIC; Project: TI_DRA821 SK EVM BRD; RoHS: RoHS; Temperature: -55°C+125°C; Tolerance: 10%; Voltage: 50V; Wattage: NA; Weight: NA; Datasheet: Y:\MIS_DATABASE\DATASHEETS\CAPACITORS\GRT155R71H104KE01.PDF
C426 = CAP: CAP CERAMIC 0.47uF 10V 10% X7R 0402; Chkd/date: PRADEEP/130623; Crtd /date: PRADEEP/130623; Custom_Duty: 15%; Customs_HS_Code: 85322990; Distributor_name: NA; Distributor_part_number: NA; Footprint Path: Y:\MIS_DATABASE\Library\ALTIUM_TOOL\PCB_FOOTPRINTS\Altium_Footprint_Lib.PcbLib; Height: 0.55MM; Library Path: Y:\MIS_DATABASE\Library\ALTIUM_TOOL\SCHEMATICS_PARTS\MS_DISCRETE_Library.schlib; Mfr_name: MURATA; Mfr_part_number: GRT155R71A474KE01; Mistral Part No: 120022060027-R; Package: 0402; Part_type: CAPACITORS\CERAMIC; Project: AM62P_SK; RoHS: RoHS; Temperature: -55°C+125°C; Tolerance: 10%; Voltage: 10V; Wattage: NA; Weight: 3.1mg; Datasheet: Y:\MIS_DATABASE\DATASHEETS\CAPACITORS\GRT155R71A474KE01.PDF
C430 C431 = CAP: CAP CERAMIC 47uF 10V 10% X5R AUTO 1206; Chkd/date: MANIRAJA/311221; Crtd /date: ALVY/301221; Custom_Duty: 15%; Customs_HS_Code: 85322990; Distributor_name: DIGIKEY; Distributor_part_number: 490-12438-1-ND; Footprint Path: Y:\MIS_DATABASE\Library\ALTIUM_TOOL\PCB_FOOTPRINTS\Altium_Footprint_Lib.PcbLib; Height: 1.80MM; Library Path: Y:\MIS_DATABASE\Library\ALTIUM_TOOL\SCHEMATICS_PARTS\MS_DISCRETE_Library.schlib; Mfr_name: MURATA; Mfr_part_number: GRT31CR61A476KE13L; Mistral Part No: 120021120022-R; Package: 1206; Part_type: CAPACITORS\CERAMIC; Project: AM62Q_SKEVM_BRD; RoHS: RoHS; Temperature: -55°C+85°C; Tolerance: 10%; Voltage: 10V; Wattage: NA; Weight: 27mg; Datasheet: Y:\MIS_DATABASE\DATASHEETS\CAPACITORS\GRT31CR61A476KE13.PDF
C559 = CAP: CAP CERAMIC 1uF 10V 20% X5R 0201; Chkd/date: NAVEED/070415; Crtd /date: VASANTHA/230314; Custom_Duty: 15%; Customs_HS_Code: 85322990; Distributor_name: DIGIKEY; Distributor_part_number: 1276-1324-1-ND; Footprint Path: Y:\MIS_DATABASE\Library\ALTIUM_TOOL\PCB_FOOTPRINTS\Altium_Footprint_Lib.PcbLib; Height: 0.35MM; Library Path: Y:\MIS_DATABASE\Library\ALTIUM_TOOL\SCHEMATICS_PARTS\MS_DISCRETE_Library.schlib; Mfr_name: SAMSUNG; Mfr_part_number: CL03A105MP3NSNC; Mistral Part No: 120015030003-R; Package: 0201; Part_type: CAPACITORS\CERAMIC; Project: DUET BOARDS; RoHS: RoHS; Temperature: -55°C+85°C; Tolerance: 20%; Voltage: 10V; Wattage: NA; Weight: 0.17mg; Datasheet: Y:\MIS_DATABASE\DATASHEETS\CAPACITORS\CL03A105MP3NSNC.PDF
J14 = CON_AUDIOJACK4_SJ-43514-SMT: CON AUDIO JACK 4POS FEMALE RT SMD; Chkd/date: MAZHAR/230211; Crtd /date: MUDDU/300610; Custom_Duty: 24%; Customs_HS_Code: 85369090; Distributor_name: DIGIKEY; Distributor_part_number: CP-43514SJCT-ND; Footprint Path: Y:\MIS_DATABASE\Library\ALTIUM_TOOL\PCB_FOOTPRINTS\Altium_Footprint_Lib.PcbLib; Height: 5.10MM; Library Path: Y:\MIS_DATABASE\Library\ALTIUM_TOOL\SCHEMATICS_PARTS\MS_CONNECTOR_Library.schlib; Mfr_name: CUI INC; Mfr_part_number: SJ-43514-SMT-TR; Mistral Part No: 150010060028-R; Package: SMD; Part_type: CONNECTOR\JACK; Project: PB_BUGBASE; RoHS: RoHS; Temperature: -25°C+85°C; Tolerance: NA; Voltage: NA; Wattage: NA; Weight: 1100mg; Datasheet: Y:\MIS_DATABASE\DATASHEETS\CONNECTORS\SJ-4351X-SMT.PDF
R399 = RESISTOR: RES 10K 1/20W 1% 0201; Chkd/date: VASANTHA/270117; Crtd /date: MANIRAJA/270117; Custom_Duty: 15%; Customs_HS_Code: 85332119; Distributor_name: DIGIKEY; Distributor_part_number: 311-10.0KMCT-ND; Footprint Path: Y:\MIS_DATABASE\Library\ALTIUM_TOOL\PCB_FOOTPRINTS\Altium_Footprint_Lib.PcbLib; Height: 0.26MM; Library Path: Y:\MIS_DATABASE\Library\ALTIUM_TOOL\SCHEMATICS_PARTS\MS_DISCRETE_Library.schlib; Mfr_name: YAGEO AMERICA; Mfr_part_number: RC0201FR-0710KL; Mistral Part No: 110011040018-R; Package: 0201; Part_type: RESISTORS\FIXED; Project: GOLDEN-I LITE; RoHS: RoHS; Temperature: -55°C+125°C; Tolerance: 1%; Voltage: NA; Wattage: 1/20W; Weight: 0.17mg; Datasheet: Y:\MIS_DATABASE\DATASHEETS\RESISTORS\RCXXXXL-SER_MAR18.PDF
R404-R407 R772 = RESISTOR: RES 0E 1/20W 5% 0201; Chkd/date: NAVEED/301214; Crtd /date: MUDDU/120710; Custom_Duty: 15%; Customs_HS_Code: 85332119; Distributor_name: DIGIKEY; Distributor_part_number: 311-0.0NCT-ND; Footprint Path: Y:\MIS_DATABASE\Library\ALTIUM_TOOL\PCB_FOOTPRINTS\Altium_Footprint_Lib.PcbLib; Height: 0.26MM; Library Path: Y:\MIS_DATABASE\Library\ALTIUM_TOOL\SCHEMATICS_PARTS\MS_DISCRETE_Library.schlib; Mfr_name: YAGEO AMERICA; Mfr_part_number: RC0201JR-070RL; Mistral Part No: 110010070067-R; Package: 0201; Part_type: RESISTORS\FIXED; Project: PB_BUGBASE; RoHS: RoHS; Temperature: -55°C+125°C; Tolerance: 5%; Voltage: NA; Wattage: 1/20W; Weight: 0.17mg; Datasheet: Y:\MIS_DATABASE\DATASHEETS\RESISTORS\RCXXXXL-SER_MAR18.PDF
R411 R435 = RESISTOR: RES 0E 1/16W JUMPER 0402; Chkd/date: VASANTHA/201216; Crtd /date: MUDDU/190810; Custom_Duty: 15%; Customs_HS_Code: 85332119; Distributor_name: DIGIKEY; Distributor_part_number: 541-0.0JCT-ND; Footprint Path: Y:\MIS_DATABASE\Library\ALTIUM_TOOL\PCB_FOOTPRINTS\Altium_Footprint_Lib.PcbLib; Height: 0.40MM; Library Path: Y:\MIS_DATABASE\Library\ALTIUM_TOOL\SCHEMATICS_PARTS\MS_DISCRETE_Library.schlib; Mfr_name: VISHAY; Mfr_part_number: CRCW04020000Z0ED; Mistral Part No: 110010080019-R; Package: 0402; Part_type: RESISTORS\FIXED; Project: PB_BUGBASE; RoHS: RoHS; Temperature: -55°C+155°C; Tolerance: NA; Voltage: NA; Wattage: 1/16W; Weight: 0.65mg; Datasheet: Y:\MIS_DATABASE\DATASHEETS\RESISTORS\CRCW0603.PDF
R437 = RESISTOR: RES 2.2K 1/20W 1% 0201; Chkd/date: VASANTHA/270117; Crtd /date: MANIRAJA/270117; Custom_Duty: 15%; Customs_HS_Code: 85332119; Distributor_name: DIGIKEY; Distributor_part_number: YAG2572CT-ND; Footprint Path: Y:\MIS_DATABASE\Library\ALTIUM_TOOL\PCB_FOOTPRINTS\Altium_Footprint_Lib.PcbLib; Height: 0.26MM; Library Path: Y:\MIS_DATABASE\Library\ALTIUM_TOOL\SCHEMATICS_PARTS\MS_DISCRETE_Library.schlib; Mfr_name: YAGEO AMERICA; Mfr_part_number: RC0201FR-072K2L; Mistral Part No: 110017010016-R; Package: 0201; Part_type: RESISTORS\FIXED; Project: GOLDEN-I LITE; RoHS: RoHS; Temperature: -55°C+125°C; Tolerance: 1%; Voltage: NA; Wattage: 1/20W; Weight: 0.17mg; Datasheet: Y:\MIS_DATABASE\DATASHEETS\RESISTORS\RCXXXXL-SER_MAR18.PDF
TP59 TP60 TP64 = TESTPOINT: TESTPOINT 1.0MM DRILL PTH; Chkd/date: MAZHAR/271211; Crtd /date: SHREESHAIL/041005; Distributor_name: NA; Distributor_part_number: NA; Height: NA; Mfr_name: LOCAL; Mistral Part No: 130009030938; Package: THRU-HOLE; Project: HSE; Datasheet: NA
U86 = OSC4_KC7050K: OSC 12.288MHz CMOS AUTO SMD; Chkd/date: ALVY/310521; Crtd /date: TAMILARASU/310522; Custom_Duty: 24%; Customs_HS_Code: 85437099; Distributor_name: DIGIKEY; Distributor_part_number: 478-MC2016Z12.2880C19XSHCT-ND; Footprint Path: Y:\MIS_DATABASE\Library\ALTIUM_TOOL\PCB_FOOTPRINTS\Altium_Footprint_Lib.PcbLib; Height: 0.80MM; Library Path: Y:\MIS_DATABASE\Library\ALTIUM_TOOL\SCHEMATICS_PARTS\MS_DISCRETE_Library.schlib; Mfr_name: KYOCERA; Mfr_part_number: MC2016Z12.2880C19XSH; Mistral Part No: 130022050049-R; Package: SMD; Part_type: OSCILLATORS; Project: TI_AM62A_SK_EVM; RoHS: RoHS; Temperature: -40°C+125°C; Tolerance: NA; Voltage: NA; Wattage: NA; Weight: NA; Datasheet: Y:\MIS_DATABASE\DATASHEETS\MISC\CRY_OSC\MC-Z-SER.PDF
U88 = TLV320AIC3106IRGZT_VQFN48: IC LOW-POWER STEREO AUDIO CODEC VQFN48; Chkd/date: SUHAS/261010; Crtd /date: MUDDU/150610; Custom_Duty: 15%; Customs_HS_Code: 85423100; Distributor_name: DIGIKEY; Distributor_part_number: TLV320AIC3106IRGZT-ND; Height: 1.00MM; Mfr_name: TEXAS INSTRUMENTS; Mistral Part No: 143010060003-R; Package: VQFN48; Part_type: ICS\TELECOM\CODEC; Project: CENTAURUS; RoHS: Sb/ Br FREE; Temperature: -40°C+85°C; Weight: NA; Datasheet: Y:\MIS_DATABASE\DATASHEETS\ICS\TELECOM\TLV320AIC3106IRGZT.PDF
U93 = SN74LVC1G08DBVRE4_SOT23-5: IC SINGLE 2-INPUT POSITIVE AND GATE SOT23-5; Chkd/date: SUHAS/221010; Crtd /date: USMAN/151008; Custom_Duty: 15%; Customs_HS_Code: 85423100; Distributor_name: DIGIKEY; Distributor_part_number: SN74LVC1G08DBVRE4-ND; Height: 1.45MM; Mfr_name: TEXAS INSTRUMENTS; Mistral Part No: 141009060026-R; Part_type: ICS\DIGITAL\GATES; Project: KHAN_MAIN; RoHS: Sb/ Br FREE; Temperature: -40°C+85°C; Datasheet: Y:\MIS_DATABASE\DATASHEETS\ICS\DIGITAL\GATES\SN74LVC1G08.PDF

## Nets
DGND: C4.2 C5.1 C7.2 C8.2 C10.1 C13.1 C115.2 C119.2 C124.2 C125.2 C168.2 C169.2 C170.2 C171.2 C175.2 C187.2 C188.1 C402.2 C406.2 C407.2 C409.2 C411.2 C418.2 C419.2 C424.2 C425.2 C434.2 C559.1 J1.12 J1.16 J1.24 J1.SH1 J1.SH2 J1.SH3 J1.SH4 J14.4 J20.1 J20.4 J20.7 J20.10 J20.13 J20.16 J20.19 J20.SH1 J20.SH2 R5.1 R15.2 R152.2 R153.2 R245.2 R251.2 R255.2 R328.1 R432.1 R450.1 TP64.1(TP) U3.2(GND) U5.7(GND) U8.43(EP) U50.4(GND) U86.2(CASEGND) U88.15(AVSS_ADC) U88.20(DRVSS.1) U88.21(DRVSS.2) U88.26(AVSS_DAC) U88.42(DVSS) U88.43(SELECT) U88.49(TPAD) U93.3(GND) ; also on sheet 10 11 12 13 14 15 16 17 18 19 20 21 22 23 24 25 26 27 28 29 30 31 32 33 34 35 36 37 40 41 42 43 44
VCC1V8_SYS: R411.2 ; also on sheet 13 18 19 21 34 37 40 42
VCC3V3_EXP: R293.1 R294.1 ; also on sheet 33
VCC_1V8_AUD: C409.1 C411.1 R411.1 U88.36(DVDD.1)
VCC_3V3_AUD: C124.1 C125.1 C402.1 C406.1 C407.1 C418.1 C419.1 C424.1 C425.1 C434.1 C559.2 R399.1 R402.1 R403.1 R427.2 R435.1 U86.4(VCC) U88.16(DRVDD.1) U88.17(DRVDD.2) U88.24(DRVDD.3) U88.25(AVDD_DAC) U88.44(IOVDD) U93.5(VCC)
VCC_3V3_SYS: C4.1 C5.2 C7.1 C13.2 C169.1 C170.1 C187.1 C188.2 J1.30 J1.32 J1.34 J1.36 J20.22 R16.1 R17.1 R29.1 R30.1 R31.1 R32.1 R38.1 R39.1 R278.1 R279.1 R292.1 R435.2 U3.7(VCCB) U5.14(VCC) U8.1(VCC) ; also on sheet 10 11 13 14 18 19 20 22 23 24 26 27 29 30 31 33 34 35 36 37 40 41 42 43
VCC_5V0: C171.1 C175.1 U50.2(IN) U50.3(EN2) ; also on sheet 10 11 15 33 35 41
VCC_CSI_IO: C8.1 C10.2 C168.1 J1.38 J1.40 R4.2 R245.1 R246.1 R247.2 R248.2 R249.1 U3.3(VCCA) ; also on sheet 37
AUD_RSTn: R450.2 U88.33(~{RESET}) U93.4(Y)
AUDIO_MSTRCLK: R407.1 U88.37(MCLK)
CSI0_FLEX_RXCLKN: J20.8 U8.28(D0-B)
CSI0_FLEX_RXCLKP: J20.9 U8.29(D0+B)
CSI0_FLEX_RXN0: J20.2 U8.26(D1-B)
CSI0_FLEX_RXN1: J20.5 U8.24(D2-B)
CSI0_FLEX_RXN2: J20.11 U8.22(D3-B)
CSI0_FLEX_RXN3: J20.14 U8.20(CEC_B)
CSI0_FLEX_RXP0: J20.3 U8.27(D1+B)
CSI0_FLEX_RXP1: J20.6 U8.25(D2+B)
CSI0_FLEX_RXP2: J20.12 U8.23(D3+B)
CSI0_FLEX_RXP3: J20.15 U8.21(HPD_B)
CSI0_MIPI_RXCLKN: J1.7 U8.37(D0-A)
CSI0_MIPI_RXCLKP: J1.5 U8.38(D0+A)
CSI0_MIPI_RXN0: J1.11 U8.35(D1-A)
CSI0_MIPI_RXN1: J1.15 U8.33(D2-A)
CSI0_MIPI_RXN2: J1.19 U8.31(D3-A)
CSI0_MIPI_RXN3: J1.23 U8.18(CEC_A)
CSI0_MIPI_RXP0: J1.9 U8.36(D1+A)
CSI0_MIPI_RXP1: J1.13 U8.34(D2+A)
CSI0_MIPI_RXP2: J1.17 U8.32(D3+A)
CSI0_MIPI_RXP3: J1.21 U8.19(HPD_A)
CSI0_RXCLKN: U8.6(D0-) U18.AB14(CSI0_RXCLKN)
CSI0_RXCLKP: U8.5(D0+) U18.AB13(CSI0_RXCLKP)
CSI0_RXN0: U8.8(D1-) U18.W12(CSI0_RXN0)
CSI0_RXN1: U8.11(D2-) U18.Y13(CSI0_RXN1)
CSI0_RXN2: U8.13(D3-) U18.AA13(CSI0_RXN2)
CSI0_RXN3: U8.15(CEC) U18.AB11(CSI0_RXN3)
CSI0_RXP0: U8.7(D1+) U18.W13(CSI0_RXP0)
CSI0_RXP1: U8.10(D2+) U18.Y14(CSI0_RXP1)
CSI0_RXP2: U8.12(D3+) U18.AA12(CSI0_RXP2)
CSI0_RXP3: U8.14(HPD) U18.AB10(CSI0_RXP3)
CSI0_RXRCALIB: R328.2 U18.V10(CSI0_RXRCALIB)
CSI_EN: R292.2 U8.2(EN) ; also on sheet 40
CSI_GPIO0: J20.17 ; also on sheet 37 40
CSI_GPIO1: J20.18 ; also on sheet 37 40
CSI_I2C2_nINT1: R29.2 U5.8(~{INT1})
CSI_I2C2_SCL: J20.20 R31.2 U3.8(SCL_B) U5.10(SC1)
CSI_I2C2_SDA: J20.21 R30.2 U3.1(SDA_B) U5.9(SD1)
CSI_I2C_LT_EN: R4.1 R5.2 U3.6(OE)
CSI_MIPI_GPIO0: J1.6 ; also on sheet 37
CSI_MIPI_GPIO1: J1.8 ; also on sheet 37
CSI_MIPI_GPIO2: J1.18 ; also on sheet 37
CSI_MIPI_GPIO3: J1.20 ; also on sheet 37
CSI_MIPI_GPIO4: J1.22 ; also on sheet 37
CSI_MIPI_I2C2_SCL: J1.2 R246.2 U3.5(SCL_A)
CSI_MIPI_I2C2_SDA: J1.4 R249.2 U3.4(SDA_A)
CSI_MIPI_RSTz: J1.14 R255.1 ; also on sheet 37
CSI_REFCLK: J1.10 TP1.1(TP) ; also on sheet 25
CSI_SEL1: R39.2 U8.16(SEL1)
CSI_SEL2: R38.2 U8.17(SEL2) ; also on sheet 40
CSI_VLDO_SEL: R251.1 U50.1(EN1) ; also on sheet 40
EXP_I2C2_nINT0: R17.2 U5.4(~{INT0})
EXP_I2C2_SCL: R293.2 U5.6(SC0) ; also on sheet 33
EXP_I2C2_SDA: R294.2 U5.5(SD0) ; also on sheet 33
GPIO_AUD_RSTn: R772.1 ; also on sheet 40
HPLOUT: C430.2 J14.2
HPLOUT_C: C430.1 U88.18(HPLOUT)
HPROUT: C431.2 J14.3
HPROUT_C: C431.1 U88.23(HPROUT)
LINE1L+: C414.1 TP59.1(TP)
LINE1L+_C: C414.2 U88.3(LINE1L+)
LINE1R+: C416.1 TP60.1(TP)
LINE1R+_C: C416.2 U88.5(LINE1R+)
MCASP1_ACLKX_AUD: TP56.1(TP) U88.38(BCLK) ; also on sheet 40
MCASP1_AFSX_AUD: TP52.1(TP) U88.39(WCLK) ; also on sheet 40
MCASP1_AXR0_AUD: TP57.1(TP) U88.40(DIN) ; also on sheet 40
MCASP1_AXR2_AUD: R404.1 TP51.1(TP) ; also on sheet 40
MFP0: R152.1 R403.2 U88.45(MFP0)
MFP1: R153.1 R402.2 U88.46(MFP1)
MFP2: TP55.1(TP) U88.47(MFP2)
MFP3: TP54.1(TP) U88.48(MFP3)
MIC_IN: C426.1 J14.1 R437.1 U88.12(MICDET)
RESETSTATz: U5.3(~{RESET}) U93.2(B) ; also on sheet 19 20 21 23 24 27 40 41 42
SOC_I2C1_SCL: R406.1 ; also on sheet 14 22 26 40 41 42
SOC_I2C1_SDA: R405.1 ; also on sheet 14 22 26 40 41 42
SoC_I2C2_SCL: R279.2 U5.12(SCL) ; also on sheet 32
SoC_I2C2_SDA: R278.2 U5.13(SDA) ; also on sheet 32
VLDO_CSI_1V8: R248.1 U50.5(OUT2)
VLDO_CSI_3V3: R247.1 U50.6(OUT1)
N16929396: R427.1 R432.2 R772.2 U93.1(A)
N16929458: TP62.1(TP) U88.7(LINE2L+)
N16929460: TP61.1(TP) U88.8(LINE2L-)
N16929474: R404.2 U88.41(DOUT)
N16929699: C115.1 U88.4(LINE1L-)
N16929703: C119.1 U88.6(LINE1R-)
N16929744: TP67.1(TP) U88.19(HPLCOM)
N16929747: TP66.1(TP) U88.22(HPRCOM)
N16929749: TP102.1(TP) U88.35(GPIO1)
N16929751: TP103.1(TP) U88.34(GPIO2)
N17275147: R407.2 U86.3(OUTPUT)
N17498937: R405.2 U88.2(SDA)
N17498940: R406.2 U88.1(SCL)
N18736007: C426.2 U88.14(MIC3R)
N18736028: R437.2 U88.13(MICBIAS)
N20878915: R16.2 U5.1(A0)
N20878927: R15.1 U5.2(A1)
N20878931: R32.2 U5.11(~{INT})
N23415089: R399.2 U86.1(INH)

Not connected (* = marked no-connect by the designer): J1 1* 3* 25* 26* 27* 28* 29* 31* 33* 35* 37* 39*; U8 3(SCL)* 4(SDA)* 9(NC1) 30(NC2) 39(SDA_B)* 40(SCL_B)* 41(SDA_A)* 42(SCL_A)*; U18 U11(RSVD6) V11(RSVD7); U88 9(LINE2R+)* 10(LINE2R-)* 11(MIC3L)* 27(MONO_LO+)* 28(MONO_LO-)* 29(LEFT_LO+)* 30(LEFT_LO-)* 31(RIGHT_LO+)* 32(RIGHT_LO-)*

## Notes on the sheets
sheet 38
- CSI INTERFACE
- R-Note:
  Based on the end product requirement, interface the
  CSI signals to the respective attached devices.
- SOC CSI INTERFACE
- 90E
- 90E
- 90E
- 90E
- 90E
- Reserved Pins
- Silk: CSI
- CSI - 1:2  MUX : Truth Table
- MUX_SEL_2
- FUNCTION
- LOW
- INPUT<--A port [CSI-2 Connector - J1]
- MIPI CONNECTOR
- HIGH
- INPUT<--B port [Flex Camera Connector - J20]
- (default)
- [SCL]
- [SDA]
- I2C SWITCH FOR SoC_I2C2
- [GPIO]
- [GPIO]
- [25MHz_REFCLK]
- [RESETz]
- [MOSI/GPIO]
- [SCLK/GPO]
- [CS/GPIO]
- [3V3]
- [VIO]
- R-Note :-
  All the I2C outputs are
  disabled by default
- I2C ADDRESS: 0x71
- MIPI SIDE
- SOC SIDE
- (VCCA < or = VCCB)
- CSI_VLDO_SEL
- LDO VTG
- LOW
- 1.8V (Default)
- Note: 1K res is to bleed off the voltage.
- High
- 3.3V
- Controlled through IO Expander.
sheet 39
- AUDIO CODEC
- Silk: LINE IN
- MIC + HEADPHONE
- D-Note:
  Add a pull-down of 10k near to the clock input.
- C
- D-Note:
  Add pulls for McASP interface IOs that can float.
- I2C ADDRESS: 0x1B
- AUDIO CODEC RESET
- CODEC I2C ADDRESS SELECTION
- MFP0
- MFP1
- Device Address
- 0
- 0
- 0x18
- 0
- 1
- 0x19
- C
- 1
- 0
- 0x1A
- 1
- 1
- 0x1B
